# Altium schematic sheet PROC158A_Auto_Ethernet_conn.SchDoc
size 431 x 279 mm; Date: Not shown in title block; ApprovedBy: Not shown in title block; CheckedBy: Not shown in title block; Author: Not shown in title block; CompanyName: Not shown in title block; Engineer: Not shown in title block; Organization: Not shown in title block; Address1: Not shown in title block; Address2: Not shown in title block; Address3: Not shown in title block; Address4: Not shown in title block; DocumentNumber: 15; Revision: Use project parameter SCH_Rev; SheetNumber: 15; SheetTotal: 24; PageSetup: Record=PageOptions¦CenterHorizontal=True¦CenterVertical=True¦PrintScale=1.00¦XCorrection=1.00¦YCorrection=1.00¦PrintKind=0¦BorderSize=5000000¦LeftOffset=0¦BottomOffset=0¦Orientation=2¦PaperLength=1000¦PaperWidth=1000¦Scale=100¦PaperSource=15¦PrintQuality=600¦MediaType=1¦DitherType=10¦PaperKind=Letter¦PrintScaleMode=1
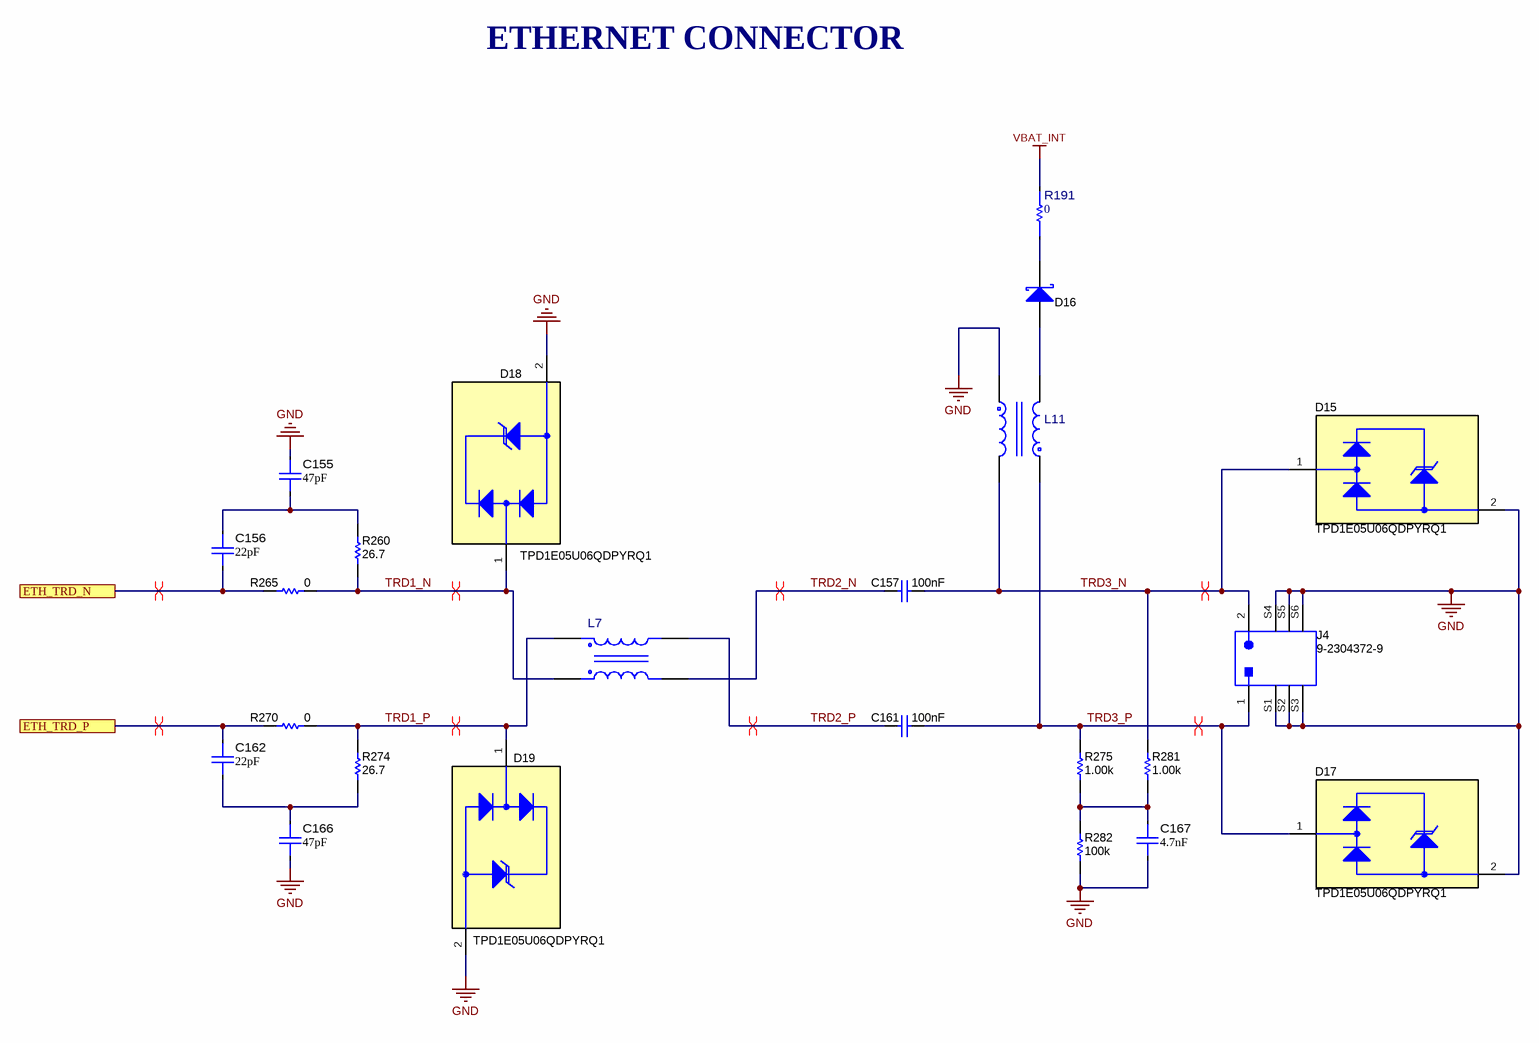
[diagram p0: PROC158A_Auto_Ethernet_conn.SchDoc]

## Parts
C155  ValueDisplayed: 47pF  [FP-KGM05ACG1H470FH_0402-MFG]  (hidden comment: KGM05ACG1H470FH)
C156  ValueDisplayed: 22pF  [FP-KGM05ACG1H220FH_0402-MFG]  (hidden comment: KGM05ACG1H220FH)
C157  Cap_F: 100nF  [0805_HV]  (hidden comment: CGA4J2X7R2A104K125AA)
C161  Cap_F: 100nF  [0805_HV]  (hidden comment: CGA4J2X7R2A104K125AA)
C162  ValueDisplayed: 22pF  [FP-KGM05ACG1H220FH_0402-MFG]  (hidden comment: KGM05ACG1H220FH)
C166  ValueDisplayed: 47pF  [FP-KGM05ACG1H470FH_0402-MFG]  (hidden comment: KGM05ACG1H470FH)
C167  ValueDisplayed: 4.7nF  [FP-CC1206KKX7RCBB472_1206-MFG]  (hidden comment: CC1206KKX7RCBB472)
D15  TPD1E05U06QDPYRQ1  [DPY0002A]
D16  PMEG6020ER,115  [SOD-123W]  (value not drawn)
D17  TPD1E05U06QDPYRQ1  [DPY0002A]
D18  TPD1E05U06QDPYRQ1  [DPY0002A]
D19  TPD1E05U06QDPYRQ1  [DPY0002A]
J4  9-2304372-9  [TE_9-2304372-9]
L7  DLW32MH101XT2  [FP-DLW32MH101XT2_1210-MFG]  (value not drawn)
L11  ADL32VHR-3R9M  [FP-ADL32VHR-3R9M_SMT_3MM2_2MM5-MFG]  (value not drawn)
R191  value 0  [FP-HCJ0805ZT0R00_0805-MFG]  (hidden comment: HCJ0805ZT0R00)
R260  ValueDisplayed: 26.7  [0402L]  (hidden comment: CRCW040226R7FKED)
R265  ValueDisplayed: 0  [0402L]  (hidden comment: CRCW04020000Z0EDHP)
R270  ValueDisplayed: 0  [0402L]  (hidden comment: CRCW04020000Z0EDHP)
R274  ValueDisplayed: 26.7  [0402L]  (hidden comment: CRCW040226R7FKED)
R275  ValueDisplayed: 1.00k  [0805L]  (hidden comment: ERJ-P06F1001V)
R281  ValueDisplayed: 1.00k  [0805L]  (hidden comment: ERJ-P06F1001V)
R282  ValueDisplayed: 100k  [0805_HV]  (hidden comment: CRCW0805100KJNEA)

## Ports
ETH_TRD_N, ETH_TRD_P

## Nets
GND: C155.1 C166.2 C167.2 D15.2(GND) D17.2(GND) D18.2(GND) D19.2(GND) J4.S1(GND) J4.S2(GND) J4.S3(GND) J4.S4(GND) J4.S5(GND) J4.S6(GND) L11.3 R282.1
VBAT_INT: R191.2
ETH_TRD_N: C156.2 R265.1 ; port ETH_TRD_N
ETH_TRD_P: C162.1 R270.1 ; port ETH_TRD_P
TRD1_N: D18.1(I/O) L7.4 R260.1 R265.2
TRD1_P: D19.1(I/O) L7.1 R270.2 R274.2
TRD2_N: C157.2 L7.3
TRD2_P: C161.2 L7.2
TRD3_N: C157.1 D15.1(I/O) J4.2 L11.4 R281.2
TRD3_P: C161.1 D17.1(I/O) J4.1 L11.1 R275.2
NetC155_2: C155.2 C156.1 R260.2
NetC162_2: C162.2 C166.1 R274.1
NetC167_1: C167.1 R275.1 R281.1 R282.2
NetD16_1: D16.1(K) R191.1
NetD16_2: D16.2(A) L11.2

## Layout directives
differential pair: ETH_TRD_N, ETH_TRD_P, TRD1_N, TRD1_P, TRD2_N, TRD2_P, TRD3_N, TRD3_P

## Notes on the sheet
- ETHERNET CONNECTOR

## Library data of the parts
C155 C166 = CMP-0120220-1: 47 pF ±1% 50V Ceramic Capacitor C0G, NP0 0402 (1005 Metric); Manufacturer: KYOCERA AVX; AEC Qualified: No; SizeZ_mm: 0.56mm; TempCo: 30ppm/°C; Value: 47pF
C156 C162 = CMP-0120219-1: 22 pF ±1% 50V Ceramic Capacitor C0G, NP0 0402 (1005 Metric); Manufacturer: KYOCERA AVX; AEC Qualified: No; SizeZ_mm: 0.56mm; TempCo: 30ppm/°C; Value: 22pF
C157 C161 = CMP-0007969-2: CAP, CERM, 0.1 uF, 100 V, +/- 10%, X7R, AEC-Q200 Grade 1, 0805; Manufacturer: TDK; TaMin_C: -55°C; ESR_ohm: 0.020726; Polarized: N; SizeAreaWB_mm2: 6.75; Value1: 0.020726 ohm; U/M: EA; Value: 0.1uF; TaMax_C: 125°C; SizeZ_mm: 1.45; SizeX_mm: 2; SizeY_mm: 1.25; Cap_Case: 0805; Value2: 100V; SizeArea_mm2: 2.5; AEC Qualified: Y; IRMS_A: 1.456A; AEC Grade: 1; AEC Category: Q200
C167 = CMP-0120216-1: 4700 pF ±10% 1000V (1kV) Ceramic Capacitor X7R 1206 (3216 Metric); Manufacturer: YAGEO; AEC Qualified: No; SizeZ_mm: 1.45mm; TempCo: 15%; Value: 4.7nF
D15 D17-D19 = CMP-0073591-4: Automotive 1-Channel Ultra-Low-Capacitance IEC ESD Protection Diode, DPY0002A (X1SON-2); Alternate Manufacturer: Texas Instruments; Alternate PartNumber: TPD1E05U06QDPYTQ1; SizeZ_mm: 0.45; SizeAreaWB_mm2: 3.2; SizeArea_mm2: 0.6; CompType: IC; AEC Category: Q200; AEC Qualified: Y; SizeX_mm: 1.0
D16 = CMP-0076989-2: Diode, Schottky, 60 V, 2 A, SOD-123W; Manufacturer: Nexperia; AEC Category: Q101; Vr_V: 60V; TJmax_C: 150°C; Green_Lifecycle: Not Set; Value1: 2A; SizeZ_mm: 1.0; Vf_V: 530mV; SizeY_mm: 1.7; Value2: 0.53V; Value: 60V; SizeArea_mm2: 5.95; SizeAreaWB_mm2: 12.15; Green_REACh: Incomplete; SizeX_mm: 3.5
J4 = CMP-0078655-1: 1 Port Header Assembly, TH; Manufacturer: TE Connectivity; Gender: Male; CompType: Connector; Shrouded: Y
L7 = CMP-0090833-1: 100μH @ 100kHz 2 Line Common Mode Choke Surface Mount 100mA DCR 3.12Ω; Manufacturer: Murata; AEC Qualified: Yes; SizeZ_mm: 2.5mm; DCR_ohm: 3.12; AEC Grade: Grade 1; Tolerance_%: -25/+50%
L11 = CMP-0098175-1: Differential Mode Choke 3.9uH 540mA 0.36Ohm 3.2x2.5x2.5mm SMT; Manufacturer: TDK; Ind_H: 3.9µH; Isat: 860mA; DCR_ohm: 0.36; Tolerance_%: 20%; SizeZ_mm: 2.5mm; Test Frequency: 100kHz; AEC Qualified: No
R191 = CMP-0091603-1: 0 Ohms Jumper 0.5W, 1/2W Chip Resistor 0805 (2012 Metric) Automotive AEC-Q200 Metal Foil; Manufacturer: Stackpole; SizeZ_mm: 0.85mm; Power: 500mW; AEC Grade: Grade 0; AEC Qualified: Yes
R260 = CMP-0026210-2: RES, 26.7, 1%, 0.063 W, AEC-Q200 Grade 0, 0402; Manufacturer: Vishay-Dale; Power_W: 63mW; TempCo: 100 ppm/C; Value_Code: 26R7; Value: 26.7; SizeX_mm: 1; SizeY_mm: 0.5; SizeZ_mm: 0.6; Value2: 0.063W; AEC Qualified: Y; VDC_V: 50V; AEC Grade: 0; AEC Category: Q200; EIA_Code: E96
R265 R270 = CMP-0081856-1: RES, 0, 0%, 0.2 W, AEC-Q200 Grade 0, 0402; Manufacturer: Vishay-Dale; SizeAreaWB_mm2: 3; SizeArea_mm2: 0.5; AEC Qualified: Y; AEC Category: Q200; Value: 0; SizeZ_mm: 0.6; Power_W: 200mW; VDC_V: 50V; Value2: 0.2W; SizeX_mm: 1
R274 = CMP-0026210-2: RES, 26.7, 1%, 0.063 W, AEC-Q200 Grade 0, 0402; Manufacturer: Vishay-Dale; Power_W: 63mW; TempCo: 100 ppm/C; Value_Code: 26R7; Value: 26.7; SizeX_mm: 1; SizeY_mm: 0.5; SizeZ_mm: 0.6; Value2: 0.063W; CompType: Resistor; AEC Qualified: Y; VDC_V: 50V; AEC Grade: 0; AEC Category: Q200; EIA_Code: E96
R275 R281 = CMP-0021848-2: RES, 1.00 k, 1%, 0.25 W, 0805; Manufacturer: Panasonic; Power_W: 250mW; TempCo: 100 ppm/C; Value_Code: 1k00; U/M: EA; Value: 1.00k; EIA_Code: E96; Res_ohm: 1k; SizeX_mm: 2; SizeY_mm: 1.25; SizeZ_mm: 1.45; Value2: 0.25W; SizeArea_mm2: 2.5; VDC_V: 400V; AEC Category: Q200
R282 = CMP-0020444-3: RES, 100 k, 5%, 0.125 W, AEC-Q200 Grade 0, 0805; Manufacturer: Vishay-Dale; Power_W: 125mW; TempCo: 200 ppm/C; Value: 100k; EIA_Code: E24; SizeX_mm: 2; SizeY_mm: 1.25; SizeZ_mm: 1.45; Value2: 0.125W; SizeArea_mm2: 2.5; AEC Qualified: Y; VDC_V: 150V; AEC Category: Q200; AEC Grade: 0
